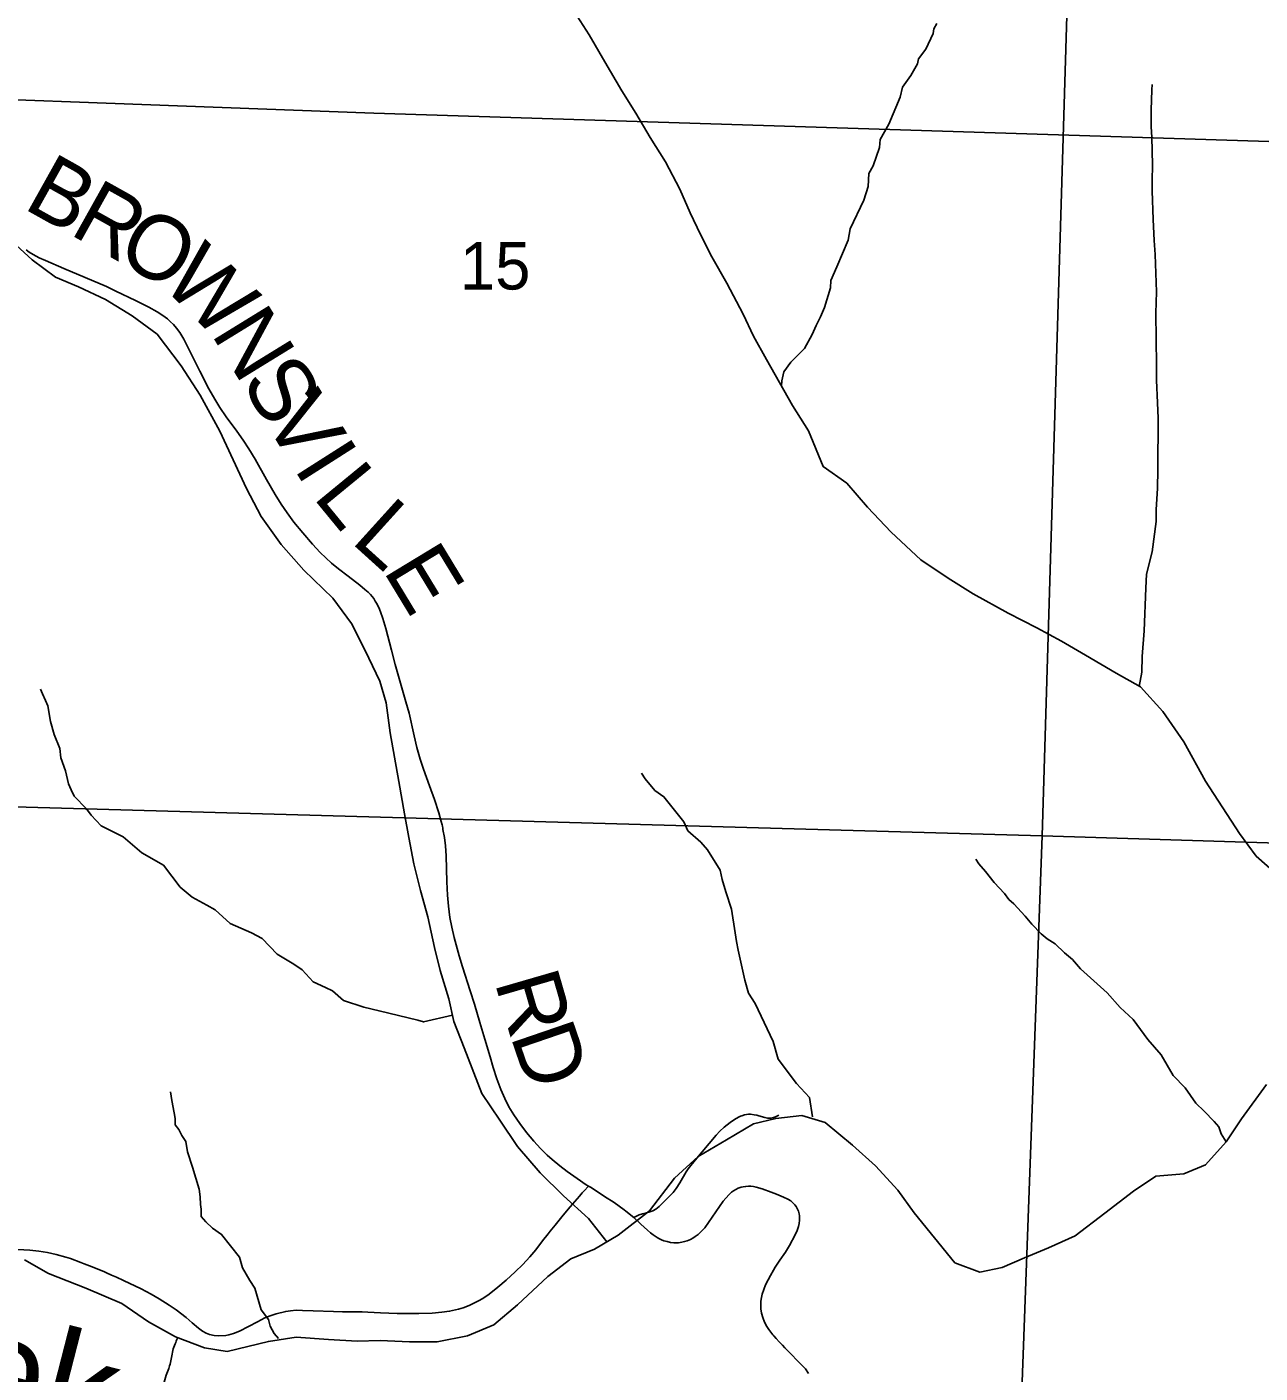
# Model space of a CAD drawing. Extents: x 6.3 to 40.3, y 9 to 31.
# Drawn here: x 10.406 to 11.496, y 26.729 to 27.918 of the extents above; entities that cross this region are included whole.
import ezdxf

# ---------------------------------------------------------------- set-up
doc = ezdxf.new("R2010")
doc.units = 0
for name, color, linetype in [('Default', 7, 'Continuous'), ('GM_X_County_Road', 7, 'Continuous'), ('GM_X_County_Road_Text', 7, 'Continuous'), ('GM_X_Minor_River', 7, 'Continuous'), ('GM_X_Minor_River_Text', 7, 'Continuous'), ('GM_X_Section', 7, 'Continuous'), ('GM_X_Section_Text', 7, 'Continuous'), ('GM_X_Township_Road', 7, 'Continuous')]:
    doc.layers.add(name, color=color, linetype=linetype)

msp = doc.modelspace()

# ---------------------------------------------------------------- linework, layer by layer
at = {"layer": 'Default'}
msp.add_lwpolyline([(13.1323, 29.9457), (8.4446, 29.9457), (8.4446, 27.9161), (8.9627, 27.9002), (9.9314, 27.8681), (10.145, 27.8635), (10.7129, 27.8423), (11.7175, 27.8106), (12.5872, 27.7766), (13.0625, 27.76), (13.0974, 28.6191), (13.1136, 29.1637), (13.1156, 29.231), (13.116, 29.2473), (13.13, 29.8856)], close=True, dxfattribs=at)
msp.add_lwpolyline([(12.5872, 27.7766), (11.7175, 27.8106), (10.7129, 27.8423), (10.145, 27.8635), (9.9314, 27.8681), (8.9627, 27.9002), (8.4446, 27.9161), (8.4446, 23.1457)], dxfattribs=at)
at = {"layer": 'GM_X_County_Road'}
for points in [[(10.9024, 26.8946), (10.9005, 26.8958), (10.8923, 26.9014), (10.8836, 26.9075), (10.8772, 26.9124), (10.8704, 26.9179), (10.8658, 26.922), (10.86, 26.9277), (10.8541, 26.9342), (10.8477, 26.9419), (10.8417, 26.9498), (10.8364, 26.9576), (10.8322, 26.9646), (10.8285, 26.9718), (10.825, 26.9798), (10.8215, 26.9892), (10.8182, 26.9993), (10.8155, 27.0088), (10.8109, 27.0243), (10.8064, 27.0392), (10.8017, 27.0552), (10.7979, 27.067), (10.791, 27.0883), (10.7881, 27.0978), (10.7838, 27.1141), (10.7816, 27.1232), (10.78, 27.1318), (10.7787, 27.1417), (10.7778, 27.1516), (10.7773, 27.1634), (10.7767, 27.1864), (10.7761, 27.195), (10.7752, 27.2024), (10.7739, 27.2096), (10.7737, 27.2107), (10.7734, 27.2124), (10.7731, 27.2136), (10.7724, 27.2165), (10.7702, 27.2242), (10.7664, 27.2359), (10.762, 27.2482), (10.7566, 27.2628), (10.7538, 27.2717), (10.7509, 27.2819), (10.7483, 27.2922), (10.7439, 27.3122), (10.7412, 27.3224), (10.7358, 27.3408), (10.7317, 27.3552), (10.7283, 27.3678), (10.7234, 27.387), (10.7207, 27.3959), (10.7187, 27.4017), (10.7171, 27.4056), (10.7151, 27.4094), (10.714, 27.4112), (10.7127, 27.4135), (10.7114, 27.4154), (10.71, 27.417), (10.7078, 27.4191), (10.705, 27.4214), (10.7003, 27.4253), (10.69, 27.4332), (10.6816, 27.4397), (10.6754, 27.4449), (10.6703, 27.4495), (10.6654, 27.4543), (10.6586, 27.4616), (10.65, 27.4715), (10.6421, 27.4811), (10.6361, 27.4891), (10.6308, 27.4968), (10.6256, 27.5053), (10.6179, 27.5188), (10.6079, 27.5367), (10.6025, 27.5457), (10.5974, 27.5534), (10.5917, 27.5615), (10.5824, 27.5739), (10.5768, 27.5822), (10.5722, 27.5896), (10.5671, 27.5989), (10.5592, 27.6143), (10.551, 27.6304), (10.5449, 27.6425), (10.5415, 27.6484), (10.5385, 27.6525), (10.5357, 27.6556), (10.5333, 27.658), (10.5304, 27.6605), (10.5265, 27.6634), (10.5214, 27.6667), (10.5139, 27.671), (10.5023, 27.6769), (10.4849, 27.6851), (10.4765, 27.6891), (10.4389, 27.7051), (10.4227, 27.7121), (10.4173, 27.7145), (10.412, 27.7173), (10.4084, 27.7196), (10.4056, 27.7215)], [(10.9424, 26.8668), (10.9355, 26.8725), (10.934, 26.8736), (10.925, 26.88), (10.9167, 26.8855), (10.9109, 26.8891), (10.9041, 26.8935), (10.9024, 26.8946)], [(11.0969, 26.729), (11.0941, 26.733), (11.0902, 26.7371), (11.0881, 26.7393), (11.0856, 26.7418), (11.0831, 26.7445), (11.0805, 26.747), (11.0797, 26.7479), (11.0771, 26.7505), (11.0758, 26.7518), (11.0737, 26.754), (11.0708, 26.7571), (11.0683, 26.7598), (11.0662, 26.7622), (11.0654, 26.7631), (11.0635, 26.7654), (11.0617, 26.7679), (11.06, 26.7705), (11.058, 26.7744), (11.0564, 26.7785), (11.0554, 26.7822), (11.055, 26.7844), (11.0548, 26.7859), (11.0547, 26.788), (11.0547, 26.7903), (11.0548, 26.7926), (11.0551, 26.7947), (11.0559, 26.799), (11.0572, 26.8032), (11.0589, 26.8073), (11.0611, 26.8118), (11.0632, 26.8157), (11.0659, 26.8203), (11.0675, 26.8229), (11.0716, 26.8291), (11.0764, 26.8362), (11.08, 26.8421), (11.0851, 26.8516), (11.0868, 26.8554), (11.0879, 26.8588), (11.0885, 26.8616), (11.0888, 26.8645), (11.0889, 26.8665), (11.0888, 26.8683), (11.0885, 26.87), (11.088, 26.8723), (11.0872, 26.8742), (11.0859, 26.8764), (11.0847, 26.8781), (11.0832, 26.8795), (11.0812, 26.8814), (11.0786, 26.883), (11.0747, 26.8849), (11.0685, 26.8875), (11.0639, 26.8892), (11.0559, 26.8921), (11.0506, 26.8936), (11.0481, 26.8942), (11.0459, 26.8944), (11.0437, 26.8944), (11.0413, 26.8943), (11.0392, 26.8939), (11.0372, 26.8935), (11.0346, 26.8927), (11.0325, 26.8916), (11.0306, 26.8905), (11.0287, 26.8891), (11.0263, 26.8869), (11.0214, 26.8813), (11.0085, 26.8623), (11.0051, 26.8578), (11.0021, 26.8545), (10.9994, 26.8519), (10.9968, 26.85), (10.9946, 26.8485), (10.9925, 26.8474), (10.9895, 26.8462), (10.9874, 26.8455), (10.9849, 26.8449), (10.9821, 26.8445), (10.98, 26.8443), (10.9779, 26.8444), (10.9749, 26.8448), (10.9718, 26.8455), (10.9691, 26.8462), (10.9668, 26.8471), (10.9645, 26.8483), (10.9632, 26.8491), (10.9614, 26.8502), (10.9595, 26.8516), (10.9573, 26.8533), (10.9545, 26.8557), (10.9488, 26.861), (10.9424, 26.8668)]]:
    msp.add_lwpolyline(points, dxfattribs=at)
at = {"layer": 'GM_X_Minor_River'}
for points in [[(11.5142, 27.1669), (11.4923, 27.1861), (11.4775, 27.2061), (11.4476, 27.2522), (11.4283, 27.2869), (11.4098, 27.3137), (11.3901, 27.3356), (11.3685, 27.3477), (11.3416, 27.3636), (11.3204, 27.376), (11.2985, 27.3877), (11.2731, 27.4006), (11.2424, 27.4176), (11.2201, 27.4315), (11.1959, 27.4478), (11.1697, 27.4723), (11.1489, 27.4942), (11.1308, 27.5153), (11.1099, 27.5301), (11.0967, 27.5618), (11.0827, 27.584), (11.0596, 27.6248), (11.0482, 27.6452), (11.0392, 27.6648), (11.0248, 27.692), (11.0115, 27.7154), (11.0013, 27.7351), (10.9922, 27.7543), (10.9831, 27.7751), (10.9706, 27.7993), (10.957, 27.8208), (10.9442, 27.8423), (10.932, 27.8619), (10.9169, 27.8876), (10.9029, 27.9114), (10.887, 27.9363)], [(11.0729, 27.6013), (11.0731, 27.6058), (11.0749, 27.6138), (11.0813, 27.6222), (11.0933, 27.6345), (11.1, 27.6467), (11.1037, 27.6547), (11.1074, 27.6624), (11.1108, 27.6707), (11.1163, 27.6879), (11.1166, 27.6944), (11.1218, 27.7066), (11.1318, 27.7302), (11.1336, 27.7401), (11.1458, 27.7653), (11.1495, 27.7775), (11.1501, 27.7889), (11.1539, 27.7958), (11.1594, 27.8118), (11.1601, 27.819), (11.1679, 27.8324), (11.1779, 27.8565), (11.1797, 27.8652), (11.1872, 27.8755), (11.1932, 27.8859), (11.1939, 27.8904), (11.2006, 27.8989), (11.2069, 27.9126), (11.2076, 27.9168), (11.2103, 27.9214)], [(11.3889, 27.3358), (11.3914, 27.3486), (11.3916, 27.3623), (11.3933, 27.3851), (11.3948, 27.4227), (11.3954, 27.4352), (11.4005, 27.4547), (11.404, 27.4817), (11.4039, 27.4919), (11.4052, 27.5109), (11.4054, 27.5273), (11.4057, 27.5729), (11.4052, 27.5865), (11.4042, 27.6063), (11.4041, 27.6196), (11.4036, 27.6655), (11.4041, 27.6845), (11.403, 27.7175), (11.4021, 27.7297), (11.4012, 27.7483), (11.4005, 27.7737), (11.4004, 27.7825), (11.4007, 27.7965), (11.4, 27.8212), (11.3996, 27.8303), (11.3994, 27.8448), (11.4, 27.863), (11.4003, 27.8676)], [(10.9186, 26.8453), (10.9025, 26.866), (10.8805, 26.886), (10.8597, 26.9064), (10.8396, 26.9295), (10.8241, 26.9529), (10.8082, 26.9763), (10.7927, 27.0166), (10.7836, 27.04), (10.779, 27.0601), (10.7715, 27.085), (10.7665, 27.1053), (10.7605, 27.1325), (10.7541, 27.1556), (10.748, 27.1793), (10.7438, 27.2024), (10.74, 27.2235), (10.7348, 27.2518), (10.7272, 27.2948), (10.7238, 27.3213), (10.7181, 27.3405), (10.7052, 27.3677), (10.6931, 27.3915), (10.6765, 27.4138), (10.6511, 27.4387), (10.631, 27.4613), (10.6132, 27.4859), (10.6004, 27.5108), (10.5769, 27.5614), (10.5595, 27.5931), (10.5425, 27.6191), (10.5213, 27.6471), (10.4993, 27.6633), (10.4758, 27.6777), (10.452, 27.689), (10.4315, 27.6973), (10.4111, 27.7128), (10.3861, 27.7354)], [(10.7824, 27.0454), (10.7567, 27.0395), (10.7517, 27.041), (10.743, 27.0432), (10.7175, 27.0493), (10.7041, 27.0526), (10.6859, 27.0585), (10.6763, 27.0671), (10.6702, 27.0701), (10.6591, 27.0749), (10.6495, 27.0855), (10.6422, 27.0907), (10.6273, 27.0993), (10.6143, 27.1132), (10.6047, 27.1184), (10.586, 27.1265), (10.5726, 27.1386), (10.5653, 27.1427), (10.5524, 27.1497), (10.5416, 27.1587), (10.527, 27.1779), (10.5079, 27.1888), (10.4914, 27.203), (10.4719, 27.2127), (10.4631, 27.2221), (10.4589, 27.2277), (10.4481, 27.239), (10.4454, 27.2447), (10.4431, 27.25), (10.4403, 27.2613), (10.4364, 27.2727), (10.4355, 27.281), (10.4304, 27.2935), (10.4273, 27.3049), (10.4249, 27.3189), (10.4229, 27.3234), (10.4202, 27.3295), (10.4182, 27.3336)], [(11.1002, 26.9558), (11.0976, 26.9729), (11.0861, 26.9853), (11.0699, 27.0068), (11.0656, 27.0223), (11.0497, 27.0559), (11.0439, 27.065), (11.0407, 27.0764), (11.0347, 27.1029), (11.0331, 27.1105), (11.0319, 27.1184), (11.0287, 27.1393), (11.0239, 27.1544), (11.0204, 27.1654), (11.0188, 27.1737), (11.0076, 27.1915), (11.0018, 27.1982), (10.9903, 27.2084), (10.9868, 27.2163), (10.9691, 27.2385), (10.9611, 27.2441), (10.9526, 27.2543), (10.9493, 27.2593)], [(11.4658, 26.9337), (11.4614, 26.9407), (11.4594, 26.9468), (11.4552, 26.9516), (11.4464, 26.9607), (11.4391, 26.9678), (11.4295, 26.9814), (11.4191, 26.9923), (11.4083, 27.0104), (11.3967, 27.0239), (11.3836, 27.0417), (11.3721, 27.0522), (11.3606, 27.0653), (11.3518, 27.0732), (11.3429, 27.0811), (11.3372, 27.0864), (11.3299, 27.0946), (11.323, 27.1006), (11.3146, 27.1085), (11.3077, 27.113), (11.3023, 27.1175), (11.2942, 27.1258), (11.2881, 27.1329), (11.2781, 27.1438), (11.2739, 27.1476), (11.27, 27.1529), (11.2608, 27.1626), (11.2531, 27.1724), (11.2473, 27.1792), (11.2446, 27.1833)], [(11.5014, 26.9842), (11.4794, 26.954), (11.4658, 26.9336), (11.4476, 26.9132), (11.4283, 26.9053), (11.4037, 26.9034), (11.384, 26.8902), (11.3586, 26.8706), (11.3325, 26.8506), (11.3087, 26.84), (11.2875, 26.8313), (11.2678, 26.8226), (11.2481, 26.8185), (11.2261, 26.8268), (11.1902, 26.8709), (11.1758, 26.891), (11.1561, 26.9125), (11.1357, 26.9306), (11.1114, 26.9506), (11.091, 26.957), (11.0679, 26.9544), (11.0482, 26.9495), (11.0244, 26.9355), (10.9994, 26.9208), (10.9785, 26.9015), (10.9562, 26.8728), (10.9286, 26.8513), (10.9078, 26.8389), (10.8869, 26.8302), (10.8665, 26.8147), (10.8396, 26.7898), (10.8188, 26.772), (10.7957, 26.7622), (10.7688, 26.757), (10.7442, 26.757), (10.7185, 26.7581), (10.698, 26.7577), (10.6727, 26.7592), (10.6443, 26.7611), (10.6197, 26.7573), (10.5833, 26.7486), (10.5633, 26.7517), (10.5375, 26.7615), (10.5137, 26.7747), (10.4902, 26.7909), (10.4584, 26.8045), (10.4254, 26.8173), (10.4042, 26.8294)], [(10.6287, 26.7599), (10.6248, 26.7643), (10.6213, 26.7707), (10.6197, 26.7768), (10.6132, 26.7854), (10.6077, 26.8044), (10.6034, 26.8112), (10.5968, 26.8225), (10.5941, 26.8319), (10.5783, 26.8519), (10.5703, 26.8575), (10.5645, 26.8631), (10.5603, 26.8677), (10.5602, 26.8741), (10.5598, 26.8783), (10.5593, 26.8851), (10.5585, 26.8919), (10.5526, 26.9112), (10.5483, 26.9249), (10.5467, 26.934), (10.5432, 26.9392), (10.5405, 26.9445), (10.5374, 26.9487), (10.5373, 26.9544), (10.5365, 26.9593), (10.5345, 26.9703), (10.5333, 26.9779)]]:
    msp.add_lwpolyline(points, dxfattribs=at)
msp.add_spline([(10.4864, 26.6606), (10.4905, 26.6664), (10.4924, 26.671), (10.5032, 26.6901), (10.5163, 26.7043), (10.5205, 26.71), (10.5215, 26.7142), (10.5264, 26.7195), (10.5294, 26.7276), (10.5316, 26.7333), (10.5331, 26.7386), (10.5345, 26.7447), (10.5356, 26.7508), (10.5378, 26.7565), (10.5393, 26.7607)], degree=3, dxfattribs=at)
at = {"layer": 'GM_X_Section'}
for points in [[(10.3378, 28.2352), (11.3334, 28.2025), (11.3031, 27.2038), (10.3113, 27.232)], [(11.3334, 28.2025), (12.3225, 28.18), (12.2889, 27.1733), (11.3031, 27.2038)], [(10.3113, 27.232), (11.3031, 27.2038), (11.2666, 26.2073), (10.2824, 26.2364)], [(11.3031, 27.2038), (12.2889, 27.1733), (12.2638, 26.3888), (12.2636, 26.3793), (12.255, 26.3481), (12.2521, 26.3409), (12.2402, 26.3255), (12.2343, 26.3163), (12.218, 26.293), (12.2028, 26.2726), (12.1883, 26.2538), (12.1742, 26.2366), (12.1608, 26.2201), (12.1526, 26.2116), (12.1361, 26.1988), (12.0826, 26.1813), (11.2666, 26.2073)]]:
    msp.add_lwpolyline(points, close=True, dxfattribs=at)
at = {"layer": 'GM_X_Township_Road'}
for points in [[(10.9424, 26.8668), (10.9472, 26.8691), (10.9503, 26.8701), (10.9536, 26.871), (10.9565, 26.8717), (10.9593, 26.8728), (10.9618, 26.8741), (10.9648, 26.8766), (10.9746, 26.8862), (10.9772, 26.8889), (10.9798, 26.8923), (10.9832, 26.8975), (10.9887, 26.9072), (10.9905, 26.9098), (10.9967, 26.9176), (11.0152, 26.9394), (11.0186, 26.943), (11.0223, 26.9465), (11.0277, 26.9508), (11.0315, 26.9535), (11.0349, 26.9555), (11.0366, 26.9562), (11.0378, 26.9567), (11.0403, 26.9574), (11.0421, 26.9578), (11.0439, 26.9581), (11.0457, 26.958), (11.0487, 26.9576), (11.0512, 26.9571)], [(11.0512, 26.9571), (11.0528, 26.9567), (11.0583, 26.9552), (11.0606, 26.9547), (11.0621, 26.9547), (11.0636, 26.9547), (11.0659, 26.9551), (11.0677, 26.9558), (11.0705, 26.9572)], [(10.3984, 26.8385), (10.409, 26.8379), (10.417, 26.8371), (10.4244, 26.8359), (10.4322, 26.8342), (10.4406, 26.8318), (10.4447, 26.8305), (10.4541, 26.8271), (10.457, 26.826), (10.4639, 26.8232), (10.4748, 26.8187), (10.4765, 26.818), (10.481, 26.816), (10.4856, 26.814), (10.4918, 26.8113), (10.5074, 26.8037), (10.5161, 26.799), (10.5231, 26.7949), (10.5321, 26.7895), (10.5382, 26.7852), (10.5471, 26.7784), (10.5522, 26.7739), (10.5579, 26.7691), (10.5614, 26.7665), (10.5646, 26.7647), (10.5675, 26.7635), (10.5717, 26.7626), (10.5754, 26.7623), (10.5822, 26.7626), (10.5847, 26.7631), (10.5888, 26.7643), (10.594, 26.7664), (10.6099, 26.7748), (10.6166, 26.7781), (10.6212, 26.78), (10.6265, 26.7817), (10.635, 26.7838), (10.6392, 26.7845), (10.6442, 26.7849), (10.6498, 26.7848), (10.6591, 26.7843), (10.6771, 26.7837), (10.6852, 26.7835), (10.7025, 26.7834), (10.7075, 26.7832), (10.7186, 26.7827), (10.7334, 26.7821), (10.7402, 26.782), (10.7526, 26.7821), (10.7643, 26.7824), (10.773, 26.7831), (10.7797, 26.784), (10.7876, 26.7857), (10.7918, 26.7869), (10.7969, 26.7891), (10.8064, 26.7938), (10.8101, 26.796), (10.8147, 26.7992), (10.8225, 26.8053), (10.8296, 26.8114), (10.8378, 26.8189), (10.8444, 26.8254), (10.8507, 26.8322), (10.8558, 26.8383), (10.8618, 26.8461), (10.8667, 26.8524), (10.8686, 26.8548), (10.8729, 26.8601), (10.88, 26.8688), (10.8864, 26.8763), (10.8944, 26.8858), (10.8968, 26.8886), (10.8985, 26.8904), (10.9024, 26.8946)]]:
    msp.add_lwpolyline(points, dxfattribs=at)

# ---------------------------------------------------------------- texts
at = {"layer": 'GM_X_County_Road_Text'}
for s, rotation, p in [('B', 330.8123, (10.4019, 27.7588)), ('R', 330.8146, (10.4427, 27.736)), ('O', 330.6057, (10.4833, 27.7133)), ('W', 315.4343, (10.5237, 27.6912)), ('N', 301.586, (10.5684, 27.6478)), ('S', 301.4861, (10.5946, 27.6052)), ('V', 301.5169, (10.6146, 27.5725)), ('I', 302.4906, (10.6413, 27.529)), ('L', 309.3835, (10.6582, 27.5033)), ('L', 317.8741, (10.6915, 27.4638)), ('E', 301.2515, (10.7203, 27.4386)), ('R', 286.1695, (10.8193, 27.0751)), ('D', 288.9155, (10.8331, 27.0275))]:
    msp.add_text(s, height=0.0568, rotation=rotation, dxfattribs=at).set_placement(p)
at = {"layer": 'GM_X_Minor_River_Text'}
msp.add_text('Creek', height=0.0947, rotation=345.6151, dxfattribs=at).set_placement((10.1452, 26.7456))
at = {"layer": 'GM_X_Section_Text'}
msp.add_text('15', height=0.04186, rotation=0, dxfattribs=at).set_placement((10.7889, 27.6865))

doc.saveas('drawing.dxf')
